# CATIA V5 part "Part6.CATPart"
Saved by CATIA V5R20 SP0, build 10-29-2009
Part number: Part6
Bounding box of the stored display mesh (mm): x -150 to 400, y -79.813 to 429.814, z -80 to 80
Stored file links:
  E:\新建文件夹 (2)\Part6.CATPart
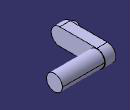
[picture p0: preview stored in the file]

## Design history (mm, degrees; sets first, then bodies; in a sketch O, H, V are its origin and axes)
Body1 (main body)
  Sketch1 on yz-plane, origin (0, 0, 0), H (0, 1, 0), V (0, 0, 1)
    arc A1 centre (0, 0) radius 80 from (0, 80) to (0, -80) ccw
    arc A2 centre (350, 0) radius 80 from (350, -80) to (350, 80) ccw
    line L1 (350, 80) -> (0, 80)
    line L2 (0, -80) -> (350, -80)
    point P4 (0, -80)
    tangency: L1 A1, L2 A2, L1 A2
    coincidence: P4 V
    horizontal: L2 H
  Pad1: profile Sketch1, direction (-1, 0, 0), length 100
  Sketch2 on end face of Pad1, origin (-100, 0, 0), H (0, -1, 0), V (0, 0, 1)
    circle A1 centre (0, 0) radius 50
    point P1 (0, 50)
    coincidence: A1 P1, P1 V
  Pad2: profile Sketch2, direction (-1, 0, 0), length 50
  Sketch3 on start face of Pad1, origin (0, 0, 0), H (0, 1, 0), V (0, 0, 1)
    circle A1 centre (350, 0) radius 75
  Pad3: profile Sketch3, direction (1, 0, 0), length 400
